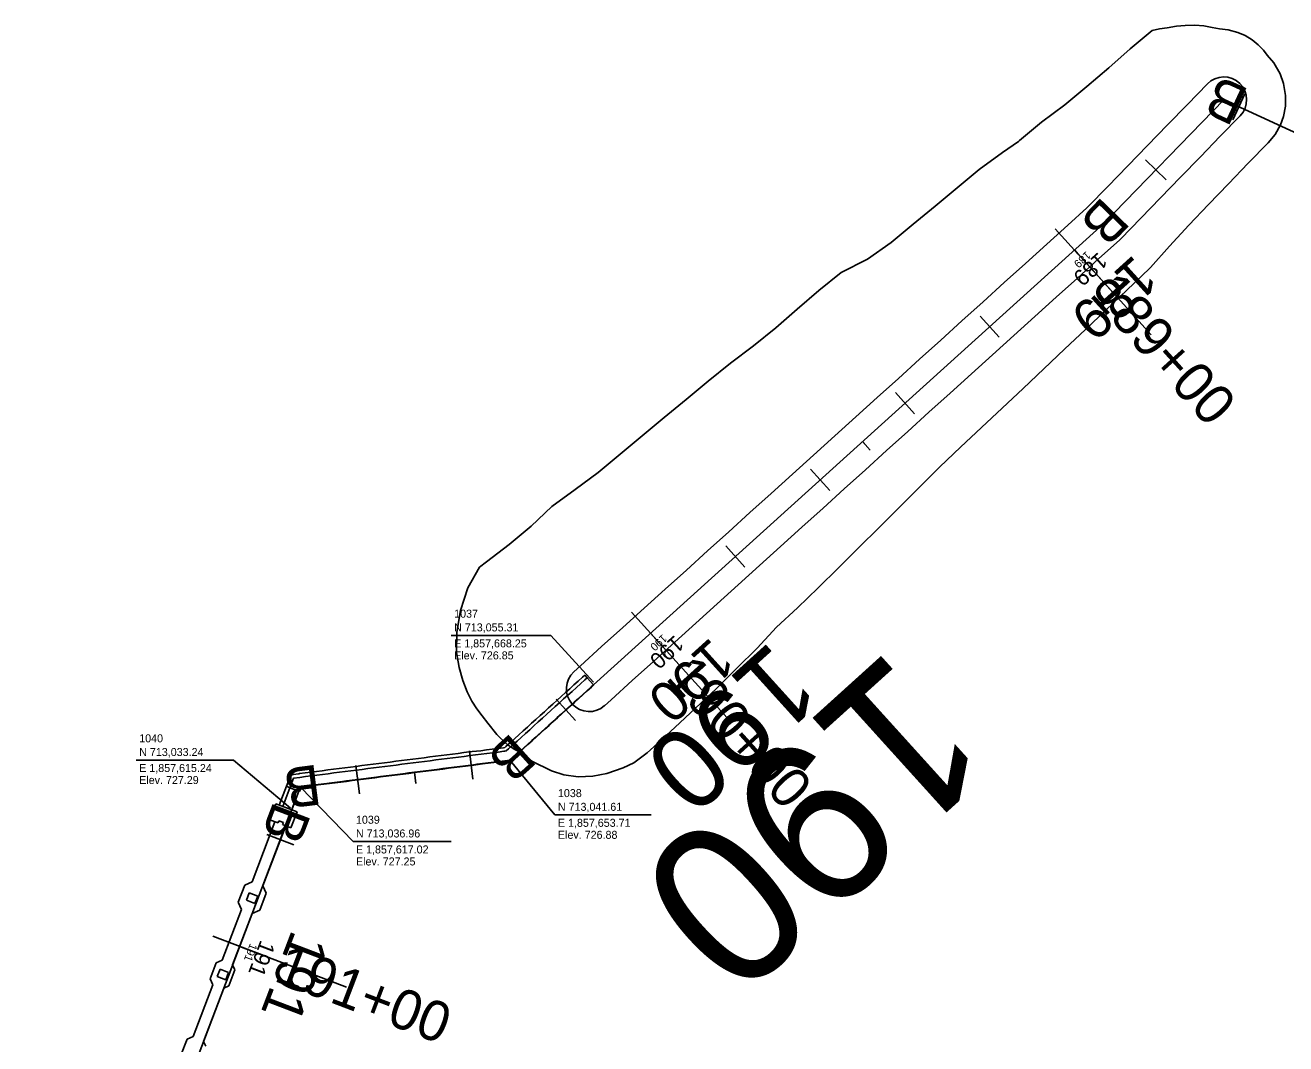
# Model space of a CAD drawing. Extents: x 1823824 to 1861612, y 706975 to 726130.
# Drawn here: x 1826100.1 to 1826320.7, y 713028.9 to 713207.2 of the extents above; entities that cross this region are included whole.
import ezdxf

# ---------------------------------------------------------------- set-up
doc = ezdxf.new("R2010")
doc.units = 0
for name, color, linetype in [('DR_X_Flood_Boundary', 7, 'Continuous'), ('GE_X_CL_10', 7, 'Continuous'), ('GE_X_CL_100', 7, 'Continuous'), ('GE_X_CL_20', 7, 'Continuous'), ('GE_X_CL_200', 7, 'Continuous'), ('GE_X_CL_50', 7, 'Continuous'), ('SC_Scratch1', 7, 'Continuous'), ('SC_Scratch5', 7, 'Continuous'), ('SC_Scratch6', 7, 'Continuous')]:
    doc.layers.add(name, color=color, linetype=linetype)

msp = doc.modelspace()

# ---------------------------------------------------------------- linework, layer by layer
at = {"layer": 'DR_X_Flood_Boundary'}
for p, q in [((1826309.82, 713194.11), (1826288.76, 713172.4)), ((1826385.95, 713158.86), (1826309.82, 713194.11)), ((1826288.76, 713172.4), (1826184.97, 713078.55)), ((1826184.97, 713078.55), (1826148.26, 713073.87)), ((1826148.26, 713073.87), (1826145.66, 713067.04)), ((1826145.66, 713067.04), (1826100.09, 712947.43))]:
    msp.add_line(p, q, dxfattribs=at)
at = {"layer": 'GE_X_CL_10'}
for p, q in [((1826283.69, 713167.82), (1826284.36, 713167.08)), ((1826246.61, 713134.29), (1826247.28, 713133.54)), ((1826209.52, 713100.75), (1826210.19, 713100.01)), ((1826168.2, 713076.41), (1826168.33, 713075.42)), ((1826137.62, 713045.93), (1826138.55, 713045.58))]:
    msp.add_line(p, q, dxfattribs=at)
at = {"layer": 'GE_X_CL_100'}
for p, q in [((1826283.69, 713167.82), (1826290.4, 713160.4)), ((1826209.52, 713100.75), (1826216.23, 713093.34)), ((1826137.62, 713045.93), (1826146.96, 713042.37))]:
    msp.add_line(p, q, dxfattribs=at)
at = {"layer": 'GE_X_CL_20'}
for p, q in [((1826283.69, 713167.82), (1826285.04, 713166.34)), ((1826246.61, 713134.29), (1826247.95, 713132.8)), ((1826209.52, 713100.75), (1826210.86, 713099.27)), ((1826168.2, 713076.41), (1826168.46, 713074.43)), ((1826137.62, 713045.93), (1826139.49, 713045.22))]:
    msp.add_line(p, q, dxfattribs=at)
at = {"layer": 'GE_X_CL_200'}
for p, q in [((1826283.69, 713167.82), (1826297.11, 713152.99)), ((1826209.52, 713100.75), (1826222.93, 713085.92)), ((1826137.62, 713045.93), (1826156.31, 713038.81))]:
    msp.add_line(p, q, dxfattribs=at)
at = {"layer": 'GE_X_CL_50'}
for p, q in [((1826283.69, 713167.82), (1826287.05, 713164.11)), ((1826209.52, 713100.75), (1826212.87, 713097.04)), ((1826137.62, 713045.93), (1826142.29, 713044.15))]:
    msp.add_line(p, q, dxfattribs=at)
at = {"layer": 'SC_Scratch1'}
for p, q in [((1826144.55, 713070.68), (1826145.8, 713073.96)), ((1826145.18, 713070.44), (1826146.42, 713073.71)), ((1826146.74, 713069.84), (1826147.98, 713073.11)), ((1826143.93, 713070.91), (1826142.86, 713068.11)), ((1826147.67, 713069.49), (1826143.93, 713070.91)), ((1826142.86, 713068.11), (1826144.35, 713067.54)), ((1826144.35, 713067.54), (1826144.5, 713067.93)), ((1826144.5, 713067.93), (1826145.26, 713067.64)), ((1826146.6, 713066.68), (1826147.67, 713069.49)), ((1826143.8, 713067.75), (1826139.8, 713057.25)), ((1826145.67, 713067.04), (1826141.67, 713056.54)), ((1826145.26, 713067.64), (1826145.11, 713067.25)), ((1826145.11, 713067.25), (1826146.6, 713066.68)), ((1826139.8, 713057.25), (1826138.51, 713056.67)), ((1826138.51, 713056.67), (1826137.38, 713053.71)), ((1826138.8, 713054.04), (1826139.29, 713055.33)), ((1826139.29, 713055.33), (1826140.77, 713054.76)), ((1826140.77, 713054.76), (1826140.28, 713053.48)), ((1826142.25, 713055.25), (1826141.12, 713052.29)), ((1826141.67, 713056.54), (1826142.25, 713055.25)), ((1826137.96, 713052.42), (1826134.58, 713043.56)), ((1826137.38, 713053.71), (1826137.96, 713052.42)), ((1826140.28, 713053.48), (1826138.8, 713054.04)), ((1826139.83, 713051.71), (1826136.39, 713042.7)), ((1826141.12, 713052.29), (1826139.83, 713051.71)), ((1826134.58, 713043.56), (1826133.51, 713043.08)), ((1826133.51, 713043.08), (1826132.44, 713040.28)), ((1826133.7, 713040.67), (1826134.19, 713041.95)), ((1826134.19, 713041.95), (1826135.67, 713041.39)), ((1826135.67, 713041.39), (1826135.18, 713040.1)), ((1826136.78, 713041.84), (1826135.71, 713039.03)), ((1826136.39, 713042.7), (1826136.78, 713041.84)), ((1826132.92, 713039.2), (1826129.49, 713030.19)), ((1826132.44, 713040.28), (1826132.92, 713039.2)), ((1826135.18, 713040.1), (1826133.7, 713040.67)), ((1826134.85, 713038.65), (1826131.3, 713029.32)), ((1826135.71, 713039.03), (1826134.85, 713038.65)), ((1826128.42, 713029.71), (1826127.35, 713026.91)), ((1826129.49, 713030.19), (1826128.42, 713029.71)), ((1826131.3, 713029.32), (1826131.69, 713028.46))]:
    msp.add_line(p, q, dxfattribs=at)
for points in [[(1826317.6, 713186.56), (1826318.81, 713188.05), (1826319.72, 713189.7), (1826320.25, 713191.18), (1826320.6, 713193), (1826320.63, 713194.84), (1826320.3, 713196.94), (1826319.68, 713198.66), (1826318.57, 713200.57), (1826317.41, 713201.92), (1826316.76, 713202.8), (1826315.85, 713203.72), (1826314.76, 713204.58), (1826313.54, 713205.33), (1826312.3, 713205.9), (1826310.58, 713206.32), (1826309.06, 713206.52), (1826307.79, 713206.76), (1826306.31, 713207.04), (1826304.73, 713207.15), (1826303.08, 713207.1), (1826301.52, 713206.97), (1826299.94, 713206.72), (1826298.55, 713206.5), (1826297.29, 713206.25)], [(1826179.56, 713112.29), (1826180.8, 713113.23), (1826184.8, 713116.27), (1826188.64, 713119.47), (1826192.27, 713122.92), (1826196.3, 713125.91), (1826200.34, 713128.9), (1826204.19, 713132.1), (1826208.02, 713135.32), (1826211.9, 713138.48), (1826215.76, 713141.67), (1826219.61, 713144.86), (1826223.53, 713147.98), (1826227.51, 713151.04), (1826231.41, 713154.17), (1826235.2, 713157.44), (1826238.98, 713160.71), (1826242.89, 713163.85), (1826247.47, 713166.23), (1826251.62, 713169.1), (1826255.45, 713172.32), (1826259.31, 713175.51), (1826263.17, 713178.7), (1826267.02, 713181.89), (1826271.08, 713184.86), (1826273.9, 713186.81), (1826274.09, 713186.97), (1826277.92, 713190.21), (1826281.98, 713193.24), (1826285.87, 713196.44), (1826289.69, 713199.7), (1826293.47, 713203), (1826297.29, 713206.25)], [(1826306.95, 713196.89), (1826303.46, 713193.3), (1826299.98, 713189.71), (1826296.5, 713186.12), (1826293.02, 713182.54), (1826289.54, 713178.95), (1826286.06, 713175.36), (1826285.88, 713175.18), (1826282.55, 713172.18), (1826278.84, 713168.82), (1826275.13, 713165.47), (1826271.42, 713162.11), (1826267.71, 713158.76), (1826264, 713155.41), (1826260.29, 713152.05), (1826256.58, 713148.7), (1826252.88, 713145.35), (1826249.17, 713141.99), (1826245.46, 713138.64), (1826241.75, 713135.29), (1826238.04, 713131.93), (1826234.33, 713128.58), (1826230.62, 713125.23), (1826226.91, 713121.87), (1826223.21, 713118.52), (1826219.5, 713115.17), (1826215.79, 713111.81), (1826212.08, 713108.46), (1826208.37, 713105.11), (1826204.66, 713101.75), (1826200.95, 713098.4), (1826197.24, 713095.05), (1826196.1, 713094.01)], [(1826201.46, 713088.07), (1826202.61, 713089.11), (1826206.32, 713092.47), (1826210.03, 713095.82), (1826213.74, 713099.17), (1826217.45, 713102.53), (1826221.15, 713105.88), (1826224.86, 713109.23), (1826228.57, 713112.59), (1826232.28, 713115.94), (1826235.99, 713119.29), (1826239.7, 713122.65), (1826243.41, 713126), (1826247.11, 713129.35), (1826250.82, 713132.71), (1826254.53, 713136.06), (1826258.24, 713139.41), (1826261.95, 713142.77), (1826265.66, 713146.12), (1826269.37, 713149.47), (1826273.08, 713152.83), (1826276.78, 713156.18), (1826280.49, 713159.53), (1826284.2, 713162.89), (1826287.91, 713166.24), (1826291.63, 713169.61), (1826291.8, 713169.79), (1826295.28, 713173.38), (1826298.76, 713176.96), (1826302.24, 713180.55), (1826305.72, 713184.14), (1826309.21, 713187.73), (1826312.69, 713191.32)], [(1826208.95, 713079.79), (1826210.09, 713080.84), (1826213.75, 713084.25), (1826217.4, 713087.66), (1826221.04, 713091.1), (1826224.59, 713094.62), (1826228.17, 713098.12), (1826231.58, 713101.8), (1826235.23, 713105.22), (1826238.83, 713108.69), (1826242.4, 713112.21), (1826245.95, 713115.73), (1826249.5, 713119.26), (1826253.05, 713122.79), (1826256.59, 713126.33), (1826260.14, 713129.86), (1826263.76, 713133.31), (1826267.4, 713136.74), (1826271.05, 713140.16), (1826274.69, 713143.59), (1826278.32, 713147.02), (1826281.96, 713150.45), (1826285.6, 713153.89), (1826289.22, 713157.34), (1826292.86, 713160.77), (1826296.82, 713164.57), (1826296.99, 713164.75), (1826300.35, 713168.46), (1826303.73, 713172.14), (1826307.14, 713175.8), (1826310.62, 713179.39), (1826314.1, 713182.98), (1826317.6, 713186.56)], [(1826208.95, 713079.79), (1826206.57, 713078.05), (1826204.72, 713077.18), (1826201.86, 713076.18), (1826199.39, 713075.74), (1826196.87, 713075.64), (1826194.33, 713075.94), (1826192.2, 713076.67), (1826188.77, 713078.38), (1826186.61, 713080), (1826185.64, 713080.47), (1826184.4, 713081.3), (1826182.64, 713083.02), (1826181.06, 713085.03), (1826180.05, 713086.29), (1826179.14, 713087.5), (1826178.27, 713088.88), (1826177.43, 713090.5), (1826176.66, 713092.47), (1826176.04, 713094.74), (1826175.57, 713097.36), (1826175.61, 713100.94), (1826176.26, 713104.72), (1826177.56, 713108.68), (1826179.56, 713112.29)], [(1826199.51, 713092.18), (1826192.05, 713100.37), (1826174.63, 713100.37)], [(1826199.51, 713092.18), (1826192.05, 713100.37), (1826174.63, 713100.37)], [(1826197.99, 713093.4), (1826197.61, 713093.05), (1826196.87, 713092.38), (1826196.12, 713091.71), (1826195.38, 713091.04), (1826194.64, 713090.37), (1826193.9, 713089.7), (1826193.16, 713089.03), (1826192.42, 713088.35), (1826191.67, 713087.68), (1826190.93, 713087.01), (1826190.19, 713086.34), (1826189.45, 713085.67), (1826188.71, 713085), (1826187.97, 713084.33), (1826187.22, 713083.66), (1826186.48, 713082.99), (1826185.74, 713082.32), (1826185, 713081.65), (1826184.22, 713080.94), (1826183.99, 713080.73), (1826183.76, 713080.69), (1826183.26, 713080.64), (1826182.79, 713080.57), (1826181.8, 713080.44), (1826180.81, 713080.32), (1826179.82, 713080.19), (1826178.3, 713080.03), (1826178.29, 713080.03), (1826176.83, 713079.86), (1826175.84, 713079.73), (1826174.85, 713079.61), (1826173.86, 713079.48), (1826172.87, 713079.35), (1826171.88, 713079.23), (1826170.88, 713079.1), (1826169.89, 713078.97), (1826168.9, 713078.85), (1826167.91, 713078.72), (1826166.92, 713078.59), (1826165.92, 713078.47), (1826164.93, 713078.34), (1826163.94, 713078.21), (1826162.95, 713078.09), (1826161.96, 713077.96), (1826160.96, 713077.83), (1826159.97, 713077.71), (1826158.98, 713077.58), (1826157.99, 713077.45), (1826157, 713077.33), (1826156, 713077.2), (1826155.01, 713077.07), (1826154.02, 713076.95), (1826153.03, 713076.82), (1826152.04, 713076.69), (1826151.04, 713076.57), (1826150.05, 713076.44), (1826149.06, 713076.31), (1826148.07, 713076.19), (1826147.96, 713076.17), (1826146.97, 713076.05), (1826146.64, 713075.91), (1826146.44, 713075.64), (1826145.8, 713073.96)], [(1826184.24, 713080.14), (1826184.67, 713080.52), (1826185.41, 713081.19), (1826186.15, 713081.86), (1826186.89, 713082.53), (1826187.64, 713083.2), (1826188.38, 713083.87), (1826189.12, 713084.55), (1826189.86, 713085.22), (1826190.6, 713085.89), (1826191.34, 713086.56), (1826192.09, 713087.23), (1826192.83, 713087.9), (1826193.57, 713088.57), (1826194.31, 713089.24), (1826195.05, 713089.91), (1826195.8, 713090.58), (1826196.54, 713091.25), (1826197.28, 713091.92), (1826198.02, 713092.59), (1826198.41, 713092.94)], [(1826197.99, 713093.4), (1826198.41, 713092.94), (1826199.52, 713091.71), (1826199.56, 713091.66)], [(1826199.56, 713091.67), (1826199.18, 713091.32), (1826198.43, 713090.65), (1826197.69, 713089.97), (1826196.95, 713089.3), (1826196.21, 713088.63), (1826195.47, 713087.96), (1826194.72, 713087.29), (1826193.98, 713086.62), (1826193.24, 713085.95), (1826192.5, 713085.28), (1826191.76, 713084.61), (1826191.02, 713083.94), (1826190.27, 713083.27), (1826189.53, 713082.6), (1826188.79, 713081.93), (1826188.05, 713081.26), (1826187.31, 713080.59), (1826186.57, 713079.91), (1826185.82, 713079.24), (1826185.08, 713078.57), (1826185.01, 713078.51), (1826184.08, 713078.38), (1826183.09, 713078.25), (1826182.1, 713078.13), (1826181.1, 713078), (1826180.11, 713077.87), (1826178.6, 713077.68), (1826178.59, 713077.68), (1826177.14, 713077.49), (1826176.15, 713077.36), (1826175.15, 713077.23), (1826174.16, 713077.11), (1826173.17, 713076.98), (1826172.18, 713076.85), (1826171.19, 713076.73), (1826170.19, 713076.6), (1826169.2, 713076.47), (1826168.21, 713076.35), (1826167.22, 713076.22), (1826166.23, 713076.1), (1826165.23, 713075.97), (1826164.24, 713075.84), (1826163.25, 713075.72), (1826162.26, 713075.59), (1826161.27, 713075.46), (1826160.27, 713075.34), (1826159.28, 713075.21), (1826158.29, 713075.08), (1826157.3, 713074.96), (1826156.31, 713074.83), (1826155.31, 713074.7), (1826154.32, 713074.58), (1826153.33, 713074.45), (1826152.34, 713074.32), (1826151.35, 713074.2), (1826150.35, 713074.07), (1826149.36, 713073.94), (1826148.37, 713073.82), (1826148.08, 713073.06)], [(1826185.04, 713078.62), (1826185.78, 713079.29), (1826186.52, 713079.96), (1826187.27, 713080.63), (1826188.01, 713081.3), (1826188.75, 713081.97), (1826189.49, 713082.64), (1826190.23, 713083.31), (1826190.97, 713083.98), (1826191.72, 713084.66), (1826192.46, 713085.33), (1826193.2, 713086), (1826193.94, 713086.67), (1826194.68, 713087.34), (1826195.43, 713088.01), (1826196.17, 713088.68), (1826196.91, 713089.35), (1826197.65, 713090.02), (1826198.39, 713090.69), (1826199.13, 713091.36), (1826199.52, 713091.71)], [(1826146.42, 713073.71), (1826147.06, 713075.4), (1826148.15, 713075.53), (1826149.14, 713075.66), (1826150.14, 713075.78), (1826151.13, 713075.91), (1826152.12, 713076.03), (1826153.11, 713076.16), (1826154.1, 713076.29), (1826155.1, 713076.41), (1826156.09, 713076.54), (1826157.08, 713076.67), (1826158.07, 713076.79), (1826159.06, 713076.92), (1826160.06, 713077.05), (1826161.05, 713077.17), (1826162.04, 713077.3), (1826163.03, 713077.43), (1826164.02, 713077.55), (1826165.02, 713077.68), (1826166.01, 713077.81), (1826167, 713077.93), (1826167.99, 713078.06), (1826168.98, 713078.19), (1826169.98, 713078.31), (1826170.97, 713078.44), (1826171.96, 713078.57), (1826172.95, 713078.69), (1826173.94, 713078.82), (1826174.94, 713078.95), (1826175.93, 713079.07), (1826176.92, 713079.2), (1826177.91, 713079.33), (1826178.9, 713079.45), (1826179.89, 713079.58), (1826180.89, 713079.71), (1826181.88, 713079.83), (1826182.87, 713079.96), (1826183.86, 713080.09), (1826183.99, 713080.11), (1826184.24, 713080.14)], [(1826146.5, 713070.11), (1826136.56, 713078.56), (1826119.52, 713078.56)], [(1826146.5, 713070.11), (1826136.56, 713078.56), (1826119.52, 713078.56)], [(1826147.97, 713073.12), (1826148.26, 713073.87), (1826148.36, 713073.88), (1826149.35, 713074.01), (1826150.35, 713074.14), (1826151.34, 713074.26), (1826152.33, 713074.39), (1826153.32, 713074.51), (1826154.31, 713074.64), (1826155.31, 713074.77), (1826156.3, 713074.89), (1826157.29, 713075.02), (1826158.28, 713075.15), (1826159.27, 713075.27), (1826160.27, 713075.4), (1826161.26, 713075.53), (1826162.25, 713075.65), (1826163.24, 713075.78), (1826164.23, 713075.91), (1826165.23, 713076.03), (1826166.22, 713076.16), (1826167.21, 713076.29), (1826168.2, 713076.41), (1826169.19, 713076.54), (1826170.19, 713076.67), (1826171.18, 713076.79), (1826172.17, 713076.92), (1826173.16, 713077.05), (1826174.15, 713077.17), (1826175.15, 713077.3), (1826176.14, 713077.43), (1826177.13, 713077.55), (1826178.12, 713077.68), (1826178.6, 713077.74), (1826179.11, 713077.81), (1826180.11, 713077.93), (1826181.1, 713078.06), (1826182.09, 713078.19), (1826183.08, 713078.31), (1826184.07, 713078.44), (1826184.97, 713078.55), (1826185.04, 713078.62)], [(1826184.97, 713078.48), (1826192.79, 713068.97), (1826209.64, 713068.97)], [(1826184.97, 713078.48), (1826192.79, 713068.97), (1826209.64, 713068.97)], [(1826145.8, 713073.96), (1826146.42, 713073.71), (1826147.97, 713073.12), (1826148.08, 713073.06)], [(1826148.28, 713073.83), (1826157.45, 713064.31), (1826174.6, 713064.31)], [(1826148.28, 713073.83), (1826157.45, 713064.31), (1826174.6, 713064.31)]]:
    msp.add_lwpolyline(points, dxfattribs=at)
for centre, start, end in [((1826309.82, 713194.1), 315.8721, 135.8498), ((1826198.78, 713091.04), 132.1254, 312.1118)]:
    msp.add_arc(centre, 4, start, end, dxfattribs=at)
at = {"layer": 'SC_Scratch5'}
for points in [[(1826311.43, 713190.61), (1826313.53, 713195.14)], [(1826299.73, 713180.11), (1826296.14, 713183.59)], [(1826287.05, 713164.11), (1826280.34, 713171.53)], [(1826270.54, 713152.55), (1826267.18, 713156.26)], [(1826255.7, 713139.14), (1826252.35, 713142.85)], [(1826240.87, 713125.73), (1826237.51, 713129.43)], [(1826226.03, 713112.31), (1826222.68, 713116.02)], [(1826212.87, 713097.04), (1826206.17, 713104.46)], [(1826196.36, 713085.48), (1826193.01, 713089.19)], [(1826178.44, 713075.2), (1826177.81, 713080.16)], [(1826158.6, 713072.67), (1826157.97, 713077.63)], [(1826147.07, 713063.73), (1826142.4, 713065.51)], [(1826142.29, 713044.15), (1826132.94, 713047.71)]]:
    msp.add_lwpolyline(points, dxfattribs=at)

# ---------------------------------------------------------------- texts
at = {"layer": 'GE_X_CL_10'}
for s, rotation, p in [('189', 222.1198, (1826285.79, 713167.69)), ('190', 222.1198, (1826211.64, 713100.65)), ('191', 249.1458, (1826139.46, 713046.56))]:
    msp.add_text(s, height=1.4, rotation=rotation, dxfattribs=at).set_placement(p)
at = {"layer": 'GE_X_CL_100'}
msp.add_text('190', height=14, rotation=222.1198, dxfattribs=at).set_placement((1826230.74, 713099.72))
at = {"layer": 'GE_X_CL_20'}
for s, rotation, p in [('189', 222.1198, (1826287.88, 713167.56)), ('190', 222.1198, (1826213.76, 713100.55)), ('191', 249.1458, (1826141.3, 713047.18))]:
    msp.add_text(s, height=2.8, rotation=rotation, dxfattribs=at).set_placement(p)
at = {"layer": 'GE_X_CL_200'}
msp.add_text('190', height=28, rotation=222.1198, dxfattribs=at).set_placement((1826251.96, 713098.68))
at = {"layer": 'GE_X_CL_50'}
for s, rotation, p in [('189', 222.1198, (1826294.16, 713167.17)), ('190', 222.1198, (1826220.13, 713100.23)), ('191', 249.1458, (1826146.83, 713049.05))]:
    msp.add_text(s, height=7, rotation=rotation, dxfattribs=at).set_placement(p)
at = {"layer": 'SC_Scratch1'}
for s, p in [(' 1037', (1826174.63, 713103.47)), (' 1037', (1826174.63, 713103.47)), (' N 713,055.31', (1826174.63, 713101.07)), (' N 713,055.31', (1826174.63, 713101.07)), (' E 1,857,668.25', (1826174.63, 713098.27)), (' E 1,857,668.25', (1826174.63, 713098.27)), (' Elev. 726.85 ', (1826174.63, 713096.17)), (' Elev. 726.85 ', (1826174.63, 713096.17)), (' 1040', (1826119.52, 713081.66)), (' 1040', (1826119.52, 713081.66)), (' N 713,033.24', (1826119.52, 713079.26)), (' N 713,033.24', (1826119.52, 713079.26)), (' E 1,857,615.24', (1826119.52, 713076.46)), (' E 1,857,615.24', (1826119.52, 713076.46)), (' Elev. 727.29 ', (1826119.52, 713074.36)), (' Elev. 727.29 ', (1826119.52, 713074.36)), (' 1038', (1826192.79, 713072.07)), (' 1038', (1826192.79, 713072.07)), (' N 713,041.61', (1826192.79, 713069.67)), (' N 713,041.61', (1826192.79, 713069.67)), (' 1039', (1826157.45, 713067.41)), (' 1039', (1826157.45, 713067.41)), (' E 1,857,653.71', (1826192.79, 713066.87)), (' E 1,857,653.71', (1826192.79, 713066.87)), (' N 713,036.96', (1826157.45, 713065.01)), (' N 713,036.96', (1826157.45, 713065.01)), (' Elev. 726.88 ', (1826192.79, 713064.77)), (' Elev. 726.88 ', (1826192.79, 713064.77)), (' E 1,857,617.02', (1826157.45, 713062.21)), (' E 1,857,617.02', (1826157.45, 713062.21)), (' Elev. 727.25 ', (1826157.45, 713060.11)), (' Elev. 727.25 ', (1826157.45, 713060.11))]:
    msp.add_text(s, height=1.4, dxfattribs=at).set_placement(p)
at = {"layer": 'SC_Scratch5'}
for s, rotation, p in [('189+00', 312.1198, (1826286.13, 713159.91)), ('190+00', 312.1198, (1826211.95, 713092.84)), ('191+00', 339.1458, (1826143.38, 713039.99))]:
    msp.add_text(s, height=7, rotation=rotation, dxfattribs=at).set_placement(p)
at = {"layer": 'SC_Scratch6'}
for rotation, p in [(155.1591, (1826314.47, 713195.81)), (225.8626, (1826288.68, 713177.35)), (222.1198, (1826185.22, 713083.5)), (187.2742, (1826151.29, 713077.78)), (249.1455, (1826143.63, 713071.56))]:
    msp.add_text('B', height=7, rotation=rotation, dxfattribs=at).set_placement(p)

doc.saveas('drawing.dxf')
